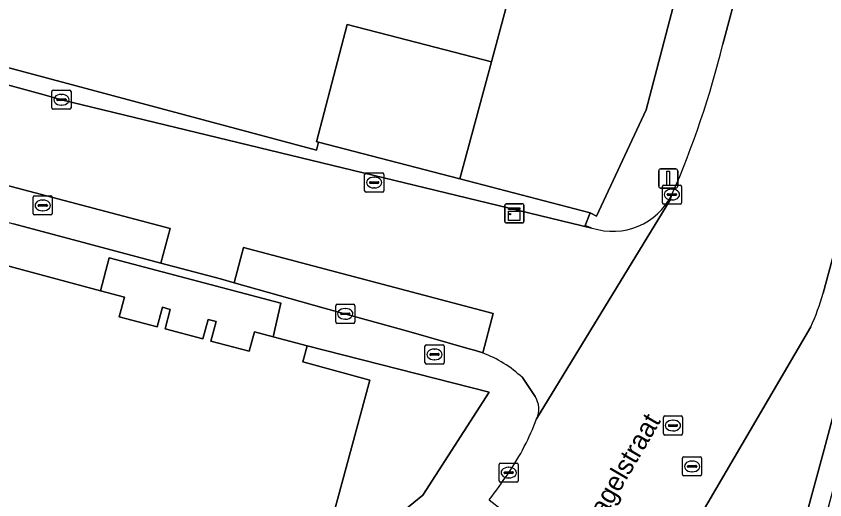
# Model space of a CAD drawing. Extents: x 160675 to 161153, y 383241 to 383714.
# Drawn here: x 160819.96 to 160862.26, y 383528.06 to 383553.38 of the extents above; entities that cross this region are included whole.
import ezdxf

# ---------------------------------------------------------------- set-up
doc = ezdxf.new("R2010")
doc.units = 0
for name, color, linetype in [('IMGEO_Brandkraan', 7, 'Continuous'), ('IMGEO_Erf', 7, 'Continuous'), ('IMGEO_Groenvoorziening', 7, 'Continuous'), ('IMGEO_Kast', 7, 'Continuous'), ('IMGEO_Kolk', 7, 'Continuous'), ('IMGEO_Lichtmast', 7, 'Continuous'), ('IMGEO_Muur', 7, 'Continuous'), ('IMGEO_Openbare_ruimte_label', 7, 'Continuous'), ('IMGEO_Pand', 7, 'Continuous'), ('IMGEO_Parkeervlak_open', 7, 'Continuous'), ('IMGEO_Rijbaan_lokaal_open', 7, 'Continuous'), ('IMGEO_Rioolput', 7, 'Continuous'), ('IMGEO_Voetpad_open', 7, 'Continuous')]:
    doc.layers.add(name, color=color, linetype=linetype)

msp = doc.modelspace()

# ---------------------------------------------------------------- linework, layer by layer
at = {"layer": 'IMGEO_Brandkraan'}
for p, q in [((160841.344, 383535.243), (160841.344, 383536.095)), ((160841.419, 383536.169), (160842.271, 383536.169)), ((160842.345, 383536.095), (160842.345, 383535.243)), ((160841.603, 383535.663), (160841.603, 383535.675)), ((160842.041, 383535.626), (160841.643, 383535.626)), ((160841.646, 383535.712), (160842.044, 383535.712)), ((160841.832, 383535.949), (160841.857, 383535.949)), ((160842.087, 383535.675), (160842.087, 383535.663)), ((160841.855, 383535.389), (160841.83, 383535.389)), ((160842.271, 383535.169), (160841.419, 383535.169))]:
    msp.add_line(p, q, dxfattribs=at)
for points in [[(160841.344, 383535.243), (160841.344, 383536.095)], [(160841.419, 383536.169), (160842.271, 383536.169)], [(160842.345, 383536.095), (160842.345, 383535.243)], [(160842.271, 383535.169), (160841.419, 383535.169)]]:
    msp.add_lwpolyline(points, dxfattribs=at)
for centre, radius, start, end in [((160841.421, 383536.093), 0.0765, 91.552, 178.448), ((160841.421, 383536.093), 0.0765, 91.552, 178.448), ((160842.269, 383536.093), 0.0765, 1.552, 88.448), ((160842.269, 383536.093), 0.0765, 1.552, 88.448), ((160841.643, 383535.672), 0.0403, 85.8775, 175.7526), ((160841.64, 383535.662), 0.0366, 178.938, 274.7102), ((160842.044, 383535.669), 0.043, 264.8664, 352.4533), ((160842.048, 383535.674), 0.0386, 1.7309, 96.639), ((160841.421, 383535.245), 0.0765, 181.552, 268.448), ((160841.421, 383535.245), 0.0765, 181.552, 268.448), ((160842.269, 383535.245), 0.0765, 271.552, 358.448), ((160842.269, 383535.245), 0.0765, 271.552, 358.448)]:
    msp.add_arc(centre, radius, start, end, dxfattribs=at)
for centre, major_axis, ratio, start_param, end_param in [((160841.831, 383535.669), (-0.387, 0.002), 0.722429, 4.712389, 7.853982), ((160841.856, 383535.669), (-0.39, 0.002), 0.717154, 1.570796, 4.712389)]:
    msp.add_ellipse(centre, major_axis=major_axis, ratio=ratio, start_param=start_param, end_param=end_param, dxfattribs=at)
at = {"layer": 'IMGEO_Erf'}
msp.add_lwpolyline([(160813.434, 383552.307), (160835.666, 383546.367), (160835.773, 383546.777), (160835.675, 383546.802), (160837.272, 383552.948), (160839.91, 383552.262), (160844.825, 383550.984), (160845.578, 383553.78), (160845.929, 383555.083), (160839.72, 383556.755), (160833.637, 383558.393), (160827.553, 383560.031), (160821.47, 383561.669), (160819.477, 383562.206)], dxfattribs=at)
msp.add_lwpolyline([(160841.228, 383528.297), (160844.706, 383533.691), (160835.176, 383536.116), (160834.961, 383535.279), (160838.46, 383534.331), (160835.583, 383523.701)], close=True, dxfattribs=at)
at = {"layer": 'IMGEO_Groenvoorziening'}
msp.add_lwpolyline([(160882.404, 383551.516), (160882.765, 383552.718), (160867.046, 383548.766), (160862.229, 383530.692), (160857.402, 383512.924), (160858.445, 383512.624), (160866.56, 383543.07), (160867.863, 383547.958), (160869.136, 383548.269)], close=True, dxfattribs=at)
at = {"layer": 'IMGEO_Kast'}
for p, q in [((160845.518, 383542.627), (160845.518, 383543.468)), ((160845.518, 383543.468), (160845.518, 383542.627)), ((160845.593, 383543.552), (160846.434, 383543.552)), ((160846.434, 383543.552), (160845.593, 383543.552)), ((160846.518, 383543.477), (160846.518, 383542.636)), ((160846.518, 383542.636), (160846.518, 383543.477)), ((160846.443, 383542.552), (160845.602, 383542.552)), ((160845.602, 383542.552), (160846.443, 383542.552))]:
    msp.add_line(p, q, dxfattribs=at)
for points in [[(160845.713, 383543.342), (160846.313, 383543.342), (160846.313, 383543.257), (160845.713, 383543.257), (160845.713, 383543.342)], [(160845.713, 383543.167), (160846.313, 383543.167), (160846.313, 383542.678), (160845.713, 383542.678), (160845.713, 383543.167)]]:
    msp.add_lwpolyline(points, dxfattribs=at)
msp.add_circle((160845.797, 383543.016), 0.0377, dxfattribs=at)
for centre, start, end in [((160845.596, 383543.474), 92.4484, 184.2845), ((160845.596, 383543.474), 92.4484, 184.2845), ((160846.44, 383543.474), 2.4484, 94.2845), ((160846.44, 383543.474), 2.4484, 94.2845), ((160845.596, 383542.63), 182.4484, 274.2845), ((160845.596, 383542.63), 182.4484, 274.2845), ((160846.44, 383542.63), 272.4484, 4.2845), ((160846.44, 383542.63), 272.4484, 4.2845)]:
    msp.add_arc(centre, 0.0779, start, end, dxfattribs=at)
at = {"layer": 'IMGEO_Kolk'}
for p, q in [((160821.825, 383548.576), (160821.825, 383549.428)), ((160821.9, 383549.502), (160822.752, 383549.502)), ((160822.313, 383549.282), (160822.338, 383549.282)), ((160822.826, 383549.428), (160822.826, 383548.576)), ((160822.084, 383548.996), (160822.084, 383549.008)), ((160822.522, 383548.959), (160822.124, 383548.959)), ((160822.127, 383549.045), (160822.525, 383549.045)), ((160822.336, 383548.722), (160822.311, 383548.722)), ((160822.568, 383549.008), (160822.568, 383548.996)), ((160822.752, 383548.502), (160821.9, 383548.502)), ((160838.188, 383544.242), (160838.188, 383545.094)), ((160838.263, 383545.168), (160839.115, 383545.168)), ((160838.676, 383544.948), (160838.701, 383544.948)), ((160839.189, 383545.094), (160839.189, 383544.242)), ((160838.447, 383544.662), (160838.447, 383544.674)), ((160838.885, 383544.625), (160838.487, 383544.625)), ((160838.49, 383544.711), (160838.888, 383544.711)), ((160838.931, 383544.674), (160838.931, 383544.662)), ((160853.84, 383544.537), (160854.692, 383544.537)), ((160839.115, 383544.168), (160838.263, 383544.168)), ((160838.699, 383544.388), (160838.674, 383544.388)), ((160853.765, 383543.611), (160853.765, 383544.463)), ((160854.067, 383544.08), (160854.465, 383544.08)), ((160854.253, 383544.317), (160854.278, 383544.317)), ((160854.766, 383544.463), (160854.766, 383543.611)), ((160820.845, 383543.044), (160820.845, 383543.896)), ((160820.92, 383543.97), (160821.772, 383543.97)), ((160821.333, 383543.75), (160821.358, 383543.75)), ((160821.846, 383543.896), (160821.846, 383543.044)), ((160854.024, 383544.031), (160854.024, 383544.043)), ((160854.462, 383543.994), (160854.064, 383543.994)), ((160854.276, 383543.757), (160854.251, 383543.757)), ((160854.508, 383544.043), (160854.508, 383544.031)), ((160821.104, 383543.464), (160821.104, 383543.476)), ((160821.542, 383543.427), (160821.144, 383543.427)), ((160821.147, 383543.513), (160821.545, 383543.513)), ((160821.588, 383543.476), (160821.588, 383543.464)), ((160854.692, 383543.537), (160853.84, 383543.537)), ((160821.772, 383542.97), (160820.92, 383542.97)), ((160821.356, 383543.19), (160821.331, 383543.19)), ((160836.673, 383537.369), (160836.673, 383538.221)), ((160836.748, 383538.295), (160837.6, 383538.295)), ((160837.674, 383538.221), (160837.674, 383537.369)), ((160836.932, 383537.789), (160836.932, 383537.801)), ((160837.37, 383537.752), (160836.972, 383537.752)), ((160836.975, 383537.838), (160837.373, 383537.838)), ((160837.161, 383538.075), (160837.186, 383538.075)), ((160837.416, 383537.801), (160837.416, 383537.789)), ((160837.6, 383537.295), (160836.748, 383537.295)), ((160837.184, 383537.515), (160837.159, 383537.515)), ((160845.224, 383529.057), (160845.224, 383529.909)), ((160845.299, 383529.983), (160846.151, 383529.983)), ((160845.712, 383529.763), (160845.737, 383529.763)), ((160846.225, 383529.909), (160846.225, 383529.057)), ((160845.483, 383529.477), (160845.483, 383529.489)), ((160845.921, 383529.44), (160845.523, 383529.44)), ((160845.526, 383529.526), (160845.924, 383529.526)), ((160845.967, 383529.489), (160845.967, 383529.477)), ((160846.151, 383528.983), (160845.299, 383528.983)), ((160845.735, 383529.203), (160845.71, 383529.203))]:
    msp.add_line(p, q, dxfattribs=at)
for points in [[(160821.825, 383548.576), (160821.825, 383549.428)], [(160821.9, 383549.502), (160822.752, 383549.502)], [(160822.826, 383549.428), (160822.826, 383548.576)], [(160822.752, 383548.502), (160821.9, 383548.502)], [(160838.188, 383544.242), (160838.188, 383545.094)], [(160838.263, 383545.168), (160839.115, 383545.168)], [(160839.189, 383545.094), (160839.189, 383544.242)], [(160853.84, 383544.537), (160854.692, 383544.537)], [(160839.115, 383544.168), (160838.263, 383544.168)], [(160853.765, 383543.611), (160853.765, 383544.463)], [(160854.766, 383544.463), (160854.766, 383543.611)], [(160820.845, 383543.044), (160820.845, 383543.896)], [(160820.92, 383543.97), (160821.772, 383543.97)], [(160821.846, 383543.896), (160821.846, 383543.044)], [(160854.692, 383543.537), (160853.84, 383543.537)], [(160821.772, 383542.97), (160820.92, 383542.97)], [(160836.673, 383537.369), (160836.673, 383538.221)], [(160836.748, 383538.295), (160837.6, 383538.295)], [(160837.674, 383538.221), (160837.674, 383537.369)], [(160837.6, 383537.295), (160836.748, 383537.295)], [(160845.224, 383529.057), (160845.224, 383529.909)], [(160845.299, 383529.983), (160846.151, 383529.983)], [(160846.225, 383529.909), (160846.225, 383529.057)], [(160846.151, 383528.983), (160845.299, 383528.983)]]:
    msp.add_lwpolyline(points, dxfattribs=at)
for centre, radius, start, end in [((160821.902, 383549.426), 0.0765, 91.552, 178.448), ((160821.902, 383549.426), 0.0765, 91.552, 178.448), ((160822.75, 383549.426), 0.0765, 1.552, 88.448), ((160822.75, 383549.426), 0.0765, 1.552, 88.448), ((160822.124, 383549.005), 0.0403, 85.8775, 175.7526), ((160822.121, 383548.995), 0.0366, 178.938, 274.7102), ((160822.525, 383549.002), 0.043, 264.8664, 352.4533), ((160822.529, 383549.007), 0.0386, 1.7309, 96.639), ((160821.902, 383548.578), 0.0765, 181.552, 268.448), ((160821.902, 383548.578), 0.0765, 181.552, 268.448), ((160822.75, 383548.578), 0.0765, 271.552, 358.448), ((160822.75, 383548.578), 0.0765, 271.552, 358.448), ((160838.265, 383545.092), 0.0765, 91.552, 178.448), ((160838.265, 383545.092), 0.0765, 91.552, 178.448), ((160839.113, 383545.092), 0.0765, 1.552, 88.448), ((160839.113, 383545.092), 0.0765, 1.552, 88.448), ((160838.487, 383544.671), 0.0403, 85.8775, 175.7526), ((160838.484, 383544.661), 0.0366, 178.938, 274.7102), ((160838.888, 383544.668), 0.043, 264.8664, 352.4533), ((160838.892, 383544.673), 0.0386, 1.7309, 96.639), ((160853.842, 383544.461), 0.0765, 91.552, 178.448), ((160853.842, 383544.461), 0.0765, 91.552, 178.448), ((160854.69, 383544.461), 0.0765, 1.552, 88.448), ((160854.69, 383544.461), 0.0765, 1.552, 88.448), ((160838.265, 383544.244), 0.0765, 181.552, 268.448), ((160838.265, 383544.244), 0.0765, 181.552, 268.448), ((160839.113, 383544.244), 0.0765, 271.552, 358.448), ((160839.113, 383544.244), 0.0765, 271.552, 358.448), ((160854.064, 383544.04), 0.0403, 85.8775, 175.7526), ((160854.469, 383544.042), 0.0386, 1.7309, 96.639), ((160820.922, 383543.894), 0.0765, 91.552, 178.448), ((160820.922, 383543.894), 0.0765, 91.552, 178.448), ((160821.77, 383543.894), 0.0765, 1.552, 88.448), ((160821.77, 383543.894), 0.0765, 1.552, 88.448), ((160854.061, 383544.03), 0.0366, 178.938, 274.7102), ((160854.465, 383544.037), 0.043, 264.8664, 352.4533), ((160821.144, 383543.473), 0.0403, 85.8775, 175.7526), ((160821.141, 383543.463), 0.0366, 178.938, 274.7102), ((160821.545, 383543.47), 0.043, 264.8664, 352.4533), ((160821.549, 383543.475), 0.0386, 1.7309, 96.639), ((160853.842, 383543.613), 0.0765, 181.552, 268.448), ((160853.842, 383543.613), 0.0765, 181.552, 268.448), ((160854.69, 383543.613), 0.0765, 271.552, 358.448), ((160854.69, 383543.613), 0.0765, 271.552, 358.448), ((160820.922, 383543.046), 0.0765, 181.552, 268.448), ((160820.922, 383543.046), 0.0765, 181.552, 268.448), ((160821.77, 383543.046), 0.0765, 271.552, 358.448), ((160821.77, 383543.046), 0.0765, 271.552, 358.448), ((160836.75, 383538.219), 0.0765, 91.552, 178.448), ((160836.75, 383538.219), 0.0765, 91.552, 178.448), ((160837.598, 383538.219), 0.0765, 1.552, 88.448), ((160837.598, 383538.219), 0.0765, 1.552, 88.448), ((160836.972, 383537.798), 0.0403, 85.8775, 175.7526), ((160836.969, 383537.788), 0.0366, 178.938, 274.7102), ((160837.373, 383537.795), 0.043, 264.8664, 352.4533), ((160837.377, 383537.8), 0.0386, 1.7309, 96.639), ((160836.75, 383537.371), 0.0765, 181.552, 268.448), ((160836.75, 383537.371), 0.0765, 181.552, 268.448), ((160837.598, 383537.371), 0.0765, 271.552, 358.448), ((160837.598, 383537.371), 0.0765, 271.552, 358.448), ((160845.301, 383529.907), 0.0765, 91.552, 178.448), ((160845.301, 383529.907), 0.0765, 91.552, 178.448), ((160846.149, 383529.907), 0.0765, 1.552, 88.448), ((160846.149, 383529.907), 0.0765, 1.552, 88.448), ((160845.523, 383529.486), 0.0403, 85.8775, 175.7526), ((160845.52, 383529.476), 0.0366, 178.938, 274.7102), ((160845.924, 383529.483), 0.043, 264.8664, 352.4533), ((160845.928, 383529.488), 0.0386, 1.7309, 96.639), ((160845.301, 383529.059), 0.0765, 181.552, 268.448), ((160845.301, 383529.059), 0.0765, 181.552, 268.448), ((160846.149, 383529.059), 0.0765, 271.552, 358.448), ((160846.149, 383529.059), 0.0765, 271.552, 358.448)]:
    msp.add_arc(centre, radius, start, end, dxfattribs=at)
for centre, major_axis, ratio, start_param, end_param in [((160822.312, 383549.002), (-0.387, 0.002), 0.722429, 4.712389, 7.853982), ((160822.337, 383549.002), (-0.39, 0.002), 0.717154, 1.570796, 4.712389), ((160838.675, 383544.668), (-0.387, 0.002), 0.722429, 4.712389, 7.853982), ((160838.7, 383544.668), (-0.39, 0.002), 0.717154, 1.570796, 4.712389), ((160854.252, 383544.037), (-0.387, 0.002), 0.722429, 4.712389, 7.853982), ((160854.277, 383544.037), (-0.39, 0.002), 0.717154, 1.570796, 4.712389), ((160821.332, 383543.47), (-0.387, 0.002), 0.722429, 4.712389, 7.853982), ((160821.357, 383543.47), (-0.39, 0.002), 0.717154, 1.570796, 4.712389), ((160837.16, 383537.795), (-0.387, 0.002), 0.722429, 4.712389, 7.853982), ((160837.185, 383537.795), (-0.39, 0.002), 0.717154, 1.570796, 4.712389), ((160845.711, 383529.483), (-0.387, 0.002), 0.722429, 4.712389, 7.853982), ((160845.736, 383529.483), (-0.39, 0.002), 0.717154, 1.570796, 4.712389)]:
    msp.add_ellipse(centre, major_axis=major_axis, ratio=ratio, start_param=start_param, end_param=end_param, dxfattribs=at)
at = {"layer": 'IMGEO_Lichtmast'}
for p, q in [((160853.675, 383545.38), (160854.465, 383545.38)), ((160854.465, 383545.38), (160853.675, 383545.38)), ((160853.575, 383544.48), (160853.575, 383545.28)), ((160853.575, 383545.28), (160853.575, 383544.48)), ((160854.565, 383545.28), (160854.565, 383544.48)), ((160854.565, 383544.48), (160854.565, 383545.28)), ((160854.465, 383544.38), (160853.675, 383544.38)), ((160853.675, 383544.38), (160854.465, 383544.38))]:
    msp.add_line(p, q, dxfattribs=at)
msp.add_lwpolyline([(160853.995, 383545.255), (160854.145, 383545.255), (160854.145, 383544.505), (160853.995, 383544.505), (160853.995, 383545.255)], dxfattribs=at)
for centre, start, end in [((160853.675, 383545.28), 90, 180), ((160853.675, 383545.28), 90, 180), ((160854.465, 383545.28), 0, 90), ((160854.465, 383545.28), 360, 90), ((160853.675, 383544.48), 180, 270), ((160853.675, 383544.48), 180, 270), ((160854.465, 383544.48), 270, 0), ((160854.465, 383544.48), 270, 0)]:
    msp.add_arc(centre, 0.1, start, end, dxfattribs=at)
at = {"layer": 'IMGEO_Muur'}
msp.add_lwpolyline([(160835.583, 383523.701), (160841.228, 383528.297)], dxfattribs=at)
at = {"layer": 'IMGEO_Pand'}
for points in [[(160857.143, 383564.601), (160857.461, 383565.816), (160849.404, 383567.986), (160845.929, 383555.083), (160845.578, 383553.78), (160844.825, 383550.984), (160843.174, 383544.853), (160849.994, 383543.081), (160850.028, 383543.072), (160850.324, 383542.913), (160852.917, 383548.465)], [(160844.825, 383550.984), (160839.91, 383552.262), (160837.272, 383552.948), (160835.675, 383546.802), (160835.773, 383546.777), (160843.174, 383544.853)]]:
    msp.add_lwpolyline(points, close=True, dxfattribs=at)
msp.add_lwpolyline([(160818.62, 383510.07), (160835.583, 383523.701), (160838.46, 383534.331), (160834.961, 383535.279), (160835.176, 383536.116), (160833.395, 383536.594), (160832.418, 383536.856), (160832.143, 383535.833), (160830.138, 383536.367), (160830.422, 383537.388), (160830.007, 383537.504), (160829.722, 383536.483), (160827.746, 383537.005), (160828.012, 383538.031), (160827.604, 383538.137), (160827.337, 383537.111), (160825.342, 383537.638), (160825.617, 383538.662), (160824.365, 383538.998), (160772.161, 383553.067)], dxfattribs=at)
at = {"layer": 'IMGEO_Parkeervlak_open'}
for points in [[(160818.163, 383544.869), (160817.716, 383543.056), (160819.812, 383542.5), (160827.531, 383540.452), (160828.009, 383542.256)], [(160831.364, 383539.424), (160836.079, 383538.099), (160840.505, 383536.875), (160843.592, 383535.981), (160843.986, 383535.876), (160844.373, 383535.746), (160844.921, 383537.811), (160831.855, 383541.275)]]:
    msp.add_lwpolyline(points, close=True, dxfattribs=at)
at = {"layer": 'IMGEO_Rijbaan_lokaal_open'}
for points in [[(160862.182, 383538.869), (160865.424, 383550.899), (160868.559, 383562.537), (160864.165, 383563.744), (160860.38, 383564.733), (160860.129, 383563.804), (160859.957, 383563.251), (160859.831, 383562.723), (160856.929, 383551.908)], [(160822.326, 383549.002), (160821.426, 383549.252), (160806.97, 383553.205)], [(160850.083, 383542.287), (160822.326, 383549.002)], [(160818.163, 383544.869), (160828.009, 383542.256), (160827.531, 383540.452), (160830.643, 383539.626), (160831.364, 383539.424), (160831.855, 383541.275), (160844.921, 383537.811), (160844.373, 383535.746)], [(160854.265, 383544.033), (160854.151, 383543.734), (160847.186, 383532.297)], [(160847.186, 383532.297), (160854.151, 383543.734), (160854.265, 383544.033)], [(160844.705, 383528.06), (160846.137, 383526.942), (160850.693, 383523.206), (160852.278, 383522.002), (160853.08, 383523.019), (160853.325, 383523.422), (160854.143, 383524.612), (160855.717, 383527.187), (160861.525, 383537.121)], [(160846.439, 383534.458), (160847.108, 383533.477)]]:
    msp.add_lwpolyline(points, dxfattribs=at)
for centre, radius, start, end in [((160809.511, 383563.561), 48.829, 336.4267, 346.1934), ((160851.165, 383545.577), 3.463, 251.7991, 333.5223), ((160850.804, 383542.148), 11.842, 334.8784, 343.9233), ((160842.201, 383529.961), 6.179, 46.6981, 69.4209), ((160846.045, 383532.814), 1.253, 335.6154, 31.9483), ((160834.957, 383536.856), 13.052, 325.5874, 339.5547), ((160821.173, 383546.022), 29.604, 322.645, 326.0282)]:
    msp.add_arc(centre, radius, start, end, dxfattribs=at)
at = {"layer": 'IMGEO_Rioolput'}
for p, q in [((160853.819, 383531.524), (160853.819, 383532.376)), ((160853.894, 383532.45), (160854.746, 383532.45)), ((160854.307, 383532.23), (160854.332, 383532.23)), ((160854.82, 383532.376), (160854.82, 383531.524)), ((160854.078, 383531.944), (160854.078, 383531.956)), ((160854.516, 383531.907), (160854.118, 383531.907)), ((160854.121, 383531.993), (160854.519, 383531.993)), ((160854.562, 383531.956), (160854.562, 383531.944)), ((160854.746, 383531.45), (160853.894, 383531.45)), ((160854.33, 383531.67), (160854.305, 383531.67)), ((160854.819, 383529.384), (160854.819, 383530.236)), ((160854.894, 383530.31), (160855.746, 383530.31)), ((160855.82, 383530.236), (160855.82, 383529.384)), ((160855.078, 383529.804), (160855.078, 383529.816)), ((160855.516, 383529.767), (160855.118, 383529.767)), ((160855.121, 383529.853), (160855.519, 383529.853)), ((160855.307, 383530.09), (160855.332, 383530.09)), ((160855.562, 383529.816), (160855.562, 383529.804)), ((160855.746, 383529.31), (160854.894, 383529.31)), ((160855.33, 383529.53), (160855.305, 383529.53))]:
    msp.add_line(p, q, dxfattribs=at)
for points in [[(160853.819, 383531.524), (160853.819, 383532.376)], [(160853.894, 383532.45), (160854.746, 383532.45)], [(160854.82, 383532.376), (160854.82, 383531.524)], [(160854.746, 383531.45), (160853.894, 383531.45)], [(160854.819, 383529.384), (160854.819, 383530.236)], [(160854.894, 383530.31), (160855.746, 383530.31)], [(160855.82, 383530.236), (160855.82, 383529.384)], [(160855.746, 383529.31), (160854.894, 383529.31)]]:
    msp.add_lwpolyline(points, dxfattribs=at)
for centre, radius, start, end in [((160853.896, 383532.374), 0.0765, 91.552, 178.448), ((160853.896, 383532.374), 0.0765, 91.552, 178.448), ((160854.744, 383532.374), 0.0765, 1.552, 88.448), ((160854.744, 383532.374), 0.0765, 1.552, 88.448), ((160854.118, 383531.953), 0.0403, 85.8775, 175.7526), ((160854.115, 383531.943), 0.0366, 178.938, 274.7102), ((160854.519, 383531.95), 0.043, 264.8664, 352.4533), ((160854.523, 383531.955), 0.0386, 1.7309, 96.639), ((160853.896, 383531.526), 0.0765, 181.552, 268.448), ((160853.896, 383531.526), 0.0765, 181.552, 268.448), ((160854.744, 383531.526), 0.0765, 271.552, 358.448), ((160854.744, 383531.526), 0.0765, 271.552, 358.448), ((160854.896, 383530.234), 0.0765, 91.552, 178.448), ((160854.896, 383530.234), 0.0765, 91.552, 178.448), ((160855.744, 383530.234), 0.0765, 1.552, 88.448), ((160855.744, 383530.234), 0.0765, 1.552, 88.448), ((160855.118, 383529.813), 0.0403, 85.8775, 175.7526), ((160855.115, 383529.803), 0.0366, 178.938, 274.7102), ((160855.519, 383529.81), 0.043, 264.8664, 352.4533), ((160855.523, 383529.815), 0.0386, 1.7309, 96.639), ((160854.896, 383529.386), 0.0765, 181.552, 268.448), ((160854.896, 383529.386), 0.0765, 181.552, 268.448), ((160855.744, 383529.386), 0.0765, 271.552, 358.448), ((160855.744, 383529.386), 0.0765, 271.552, 358.448)]:
    msp.add_arc(centre, radius, start, end, dxfattribs=at)
for centre, major_axis, ratio, start_param, end_param in [((160854.306, 383531.95), (-0.387, 0.002), 0.722429, 4.712389, 7.853982), ((160854.331, 383531.95), (-0.39, 0.002), 0.717154, 1.570796, 4.712389), ((160855.306, 383529.81), (-0.387, 0.002), 0.722429, 4.712389, 7.853982), ((160855.331, 383529.81), (-0.39, 0.002), 0.717154, 1.570796, 4.712389)]:
    msp.add_ellipse(centre, major_axis=major_axis, ratio=ratio, start_param=start_param, end_param=end_param, dxfattribs=at)
at = {"layer": 'IMGEO_Voetpad_open'}
for points in [[(160859.831, 383562.723), (160859.957, 383563.251), (160860.129, 383563.804), (160860.38, 383564.733), (160857.461, 383565.816), (160857.143, 383564.601), (160852.917, 383548.465), (160850.324, 383542.913), (160850.028, 383543.072), (160849.994, 383543.081), (160849.734, 383542.418), (160850.083, 383542.287)], [(160856.929, 383551.908), (160859.831, 383562.723)], [(160871.287, 383559.494), (160871.974, 383562.641), (160868.559, 383562.537), (160865.424, 383550.899), (160862.182, 383538.869)], [(160861.525, 383537.121), (160855.717, 383527.187), (160854.143, 383524.612), (160853.325, 383523.422), (160853.08, 383523.019), (160852.899, 383522.475), (160851.327, 383517.544), (160850.446, 383514.813), (160850.389, 383514.634), (160857.402, 383512.924), (160862.229, 383530.692), (160867.046, 383548.766), (160871.287, 383559.494)], [(160772.161, 383553.067), (160824.365, 383538.998), (160824.823, 383540.726), (160833.805, 383538.352), (160833.395, 383536.594), (160835.176, 383536.116), (160844.706, 383533.691), (160841.228, 383528.297), (160835.583, 383523.701), (160818.62, 383510.07)], [(160806.97, 383553.205), (160821.426, 383549.252), (160822.326, 383549.002), (160850.083, 383542.287), (160849.734, 383542.418), (160849.994, 383543.081), (160843.174, 383544.853), (160835.773, 383546.777), (160835.666, 383546.367), (160813.434, 383552.307)], [(160844.373, 383535.746), (160843.986, 383535.876), (160843.592, 383535.981), (160840.505, 383536.875), (160836.079, 383538.099), (160831.364, 383539.424), (160830.643, 383539.626), (160827.531, 383540.452), (160819.812, 383542.5)], [(160847.108, 383533.477), (160846.439, 383534.458)]]:
    msp.add_lwpolyline(points, dxfattribs=at)
msp.add_lwpolyline([(160833.395, 383536.594), (160833.805, 383538.352), (160824.823, 383540.726), (160824.365, 383538.998), (160825.617, 383538.662), (160825.342, 383537.638), (160827.337, 383537.111), (160827.604, 383538.137), (160828.012, 383538.031), (160827.746, 383537.005), (160829.722, 383536.483), (160830.007, 383537.504), (160830.422, 383537.388), (160830.138, 383536.367), (160832.143, 383535.833), (160832.418, 383536.856)], close=True, dxfattribs=at)
for centre, radius, start, end in [((160809.511, 383563.561), 48.829, 336.4267, 346.1934), ((160851.165, 383545.577), 3.463, 251.7991, 333.5223), ((160850.804, 383542.148), 11.842, 334.8784, 343.9233), ((160842.201, 383529.961), 6.179, 46.6981, 69.4209), ((160846.045, 383532.814), 1.253, 335.6154, 31.9483), ((160834.957, 383536.856), 13.052, 325.5874, 339.5547), ((160821.173, 383546.022), 29.604, 322.645, 326.0282)]:
    msp.add_arc(centre, radius, start, end, dxfattribs=at)

# ---------------------------------------------------------------- texts
at = {"layer": 'IMGEO_Openbare_ruimte_label'}
msp.add_text('Gagelstraat', height=1, rotation=59.7931, dxfattribs=at).set_placement((160850.224, 383526.218))

doc.saveas('drawing.dxf')
